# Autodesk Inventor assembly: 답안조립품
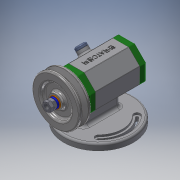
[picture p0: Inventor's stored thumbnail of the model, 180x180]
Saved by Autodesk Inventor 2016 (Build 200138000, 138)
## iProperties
Created: 2017-06
Part Number: 답안조립품
Material: 일반
Document SubType Name: Assembly
Designer: USER
Author: USER
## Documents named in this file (14)
- C:\Users\USER\Desktop\답안조립품.iam
- C:\Users\USER\Desktop\470607V1006\부품1.ipt
- C:\Users\USER\Desktop\470607V1006\V벨트풀리.ipt
- C:\Users\USER\Desktop\470607V1006\고무캡.ipt
- C:\Users\USER\Desktop\470607V1006\너트 M 8.ipt
- C:\Users\USER\Desktop\470607V1006\뒤커버.ipt
- C:\Users\USER\Desktop\470607V1006\베어링 15 x 32 x 9.ipt
- C:\Users\USER\Desktop\470607V1006\볼트 M4 x 12.ipt
- C:\Users\USER\Desktop\470607V1006\스프링와셔 8.ipt
- C:\Users\USER\Desktop\470607V1006\앞커버.ipt
- C:\Users\USER\Desktop\470607V1006\오일 실 15 25 7.ipt
- C:\Users\USER\Desktop\470607V1006\와셔 8x17.ipt
- C:\Users\USER\Desktop\470607V1006\축.ipt
- C:\Users\USER\Desktop\470607V1006\키 3 x 3 x 12.ipt
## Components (2 placed, 2 different names)
1. V벨트풀리:1
2. 고무캡:1
